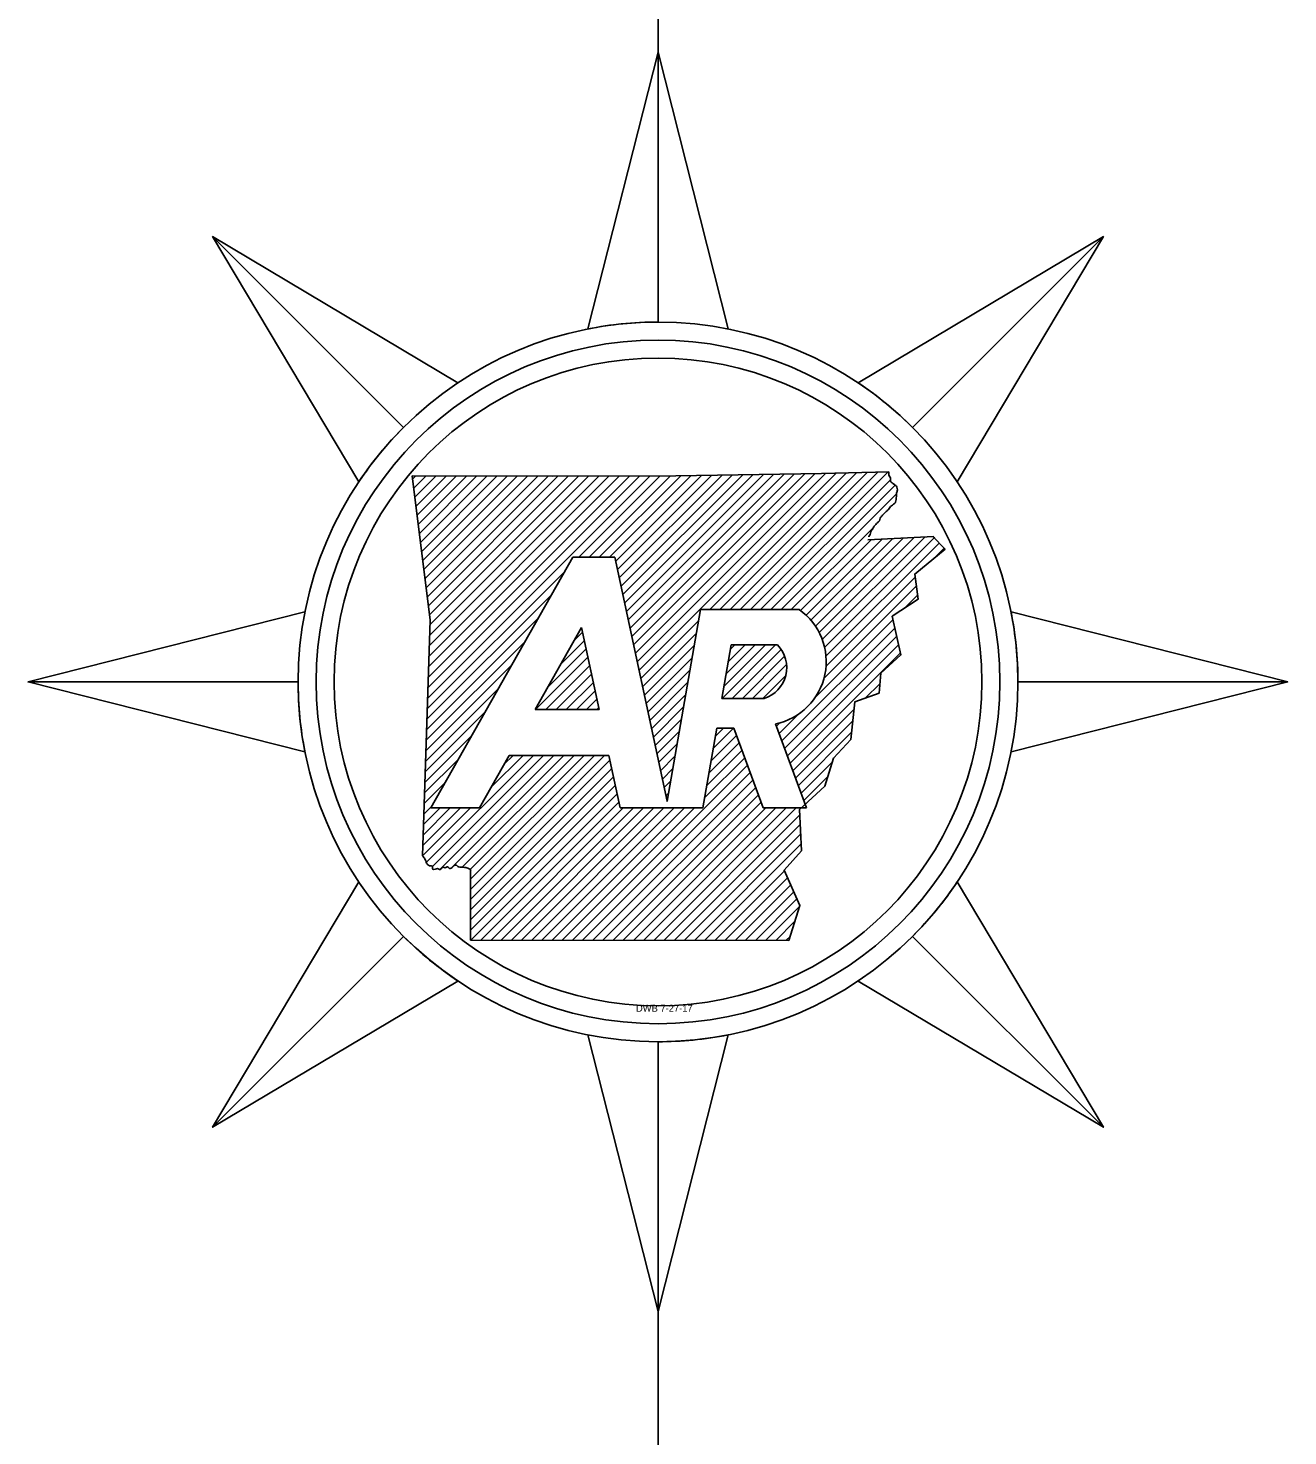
# Model space of a CAD drawing. Extents: x -4306 to 3843, y 131 to 8341.
# Drawn here: x 2356 to 2886, y 2831 to 3423 of the extents above; entities that cross this region are included whole.
import ezdxf

# ---------------------------------------------------------------- set-up
doc = ezdxf.new("R2010")
doc.units = 0
doc.layers.add('50', color=7, linetype='Continuous')

msp = doc.modelspace()

# ---------------------------------------------------------------- linework, layer by layer
at = {"layer": '50'}
for p, q in [((2621.3, 3912.98), (2621.3, 3315.55)), ((2621.3, 3412.53), (2591.83, 3296.13)), ((2621.3, 3299.03), (2621.3, 3412.53)), ((2434.03, 3334.96), (2514.29, 3254.71)), ((2514.29, 3254.71), (2434.03, 3334.96)), ((2434.03, 3334.96), (2495.5, 3231.82)), ((2808.56, 3334.96), (2705.42, 3273.49)), ((2728.3, 3254.71), (2808.56, 3334.96)), ((2728.3, 3254.71), (2808.56, 3334.96)), ((2518.14, 3232.99), (2519.48, 3234.33)), ((2518.62, 3229.19), (2523.76, 3234.32)), ((2519.09, 3225.38), (2528.03, 3234.32)), ((2519.57, 3221.57), (2532.31, 3234.32)), ((2520.04, 3217.77), (2536.59, 3234.32)), ((2520.52, 3213.96), (2540.87, 3234.31)), ((2520.99, 3210.15), (2545.15, 3234.31)), ((2521.46, 3206.35), (2549.42, 3234.31)), ((2521.94, 3202.54), (2553.7, 3234.3)), ((2522.41, 3198.74), (2557.98, 3234.3)), ((2522.89, 3194.93), (2562.26, 3234.3)), ((2523.36, 3191.12), (2566.53, 3234.3)), ((2523.83, 3187.32), (2570.81, 3234.29)), ((2524.31, 3183.51), (2575.09, 3234.29)), ((2524.45, 3140.85), (2617.98, 3234.38)), ((2524.6, 3145.28), (2613.69, 3234.37)), ((2524.74, 3149.71), (2609.4, 3234.36)), ((2524.78, 3179.7), (2579.37, 3234.3)), ((2524.89, 3154.13), (2605.11, 3234.35)), ((2525.04, 3158.56), (2600.82, 3234.34)), ((2525.18, 3162.99), (2596.53, 3234.33)), ((2525.26, 3175.9), (2583.66, 3234.3)), ((2525.33, 3167.41), (2592.24, 3234.32)), ((2525.48, 3171.84), (2587.95, 3234.31)), ((2588.01, 3200.13), (2622.27, 3234.39)), ((2592.29, 3200.13), (2626.56, 3234.4)), ((2596.57, 3200.13), (2630.87, 3234.43)), ((2600.85, 3200.13), (2635.22, 3234.5)), ((2603.52, 3198.52), (2639.57, 3234.57)), ((2604.27, 3194.99), (2643.92, 3234.63)), ((2605.03, 3191.47), (2648.26, 3234.7)), ((2605.78, 3187.94), (2652.61, 3234.77)), ((2606.54, 3184.42), (2656.96, 3234.84)), ((2607.29, 3180.89), (2661.31, 3234.9)), ((2608.05, 3177.36), (2665.65, 3234.97)), ((2608.8, 3173.84), (2670, 3235.04)), ((2609.56, 3170.31), (2674.35, 3235.11)), ((2610.31, 3166.79), (2678.7, 3235.17)), ((2611.06, 3163.26), (2683.05, 3235.24)), ((2611.82, 3159.74), (2687.39, 3235.31)), ((2612.57, 3156.21), (2691.75, 3235.39)), ((2613.33, 3152.68), (2696.14, 3235.49)), ((2643.06, 3178.14), (2700.52, 3235.59)), ((2647.34, 3178.14), (2704.9, 3235.7)), ((2651.62, 3178.14), (2709.28, 3235.8)), ((2655.9, 3178.14), (2713.66, 3235.9)), ((2660.18, 3178.14), (2718.05, 3236)), ((2664.46, 3178.14), (2719, 3232.67)), ((2668.74, 3178.14), (2721.07, 3230.46)), ((2673.02, 3178.14), (2721.62, 3226.74)), ((2677.3, 3178.14), (2711.85, 3212.68)), ((2690.36, 3165.52), (2733.57, 3208.72)), ((2681.19, 3177.75), (2711.01, 3207.56)), ((2683.53, 3175.8), (2715.52, 3207.79)), ((2685.62, 3173.61), (2720.03, 3208.02)), ((2687.47, 3171.18), (2724.54, 3208.26)), ((2689.06, 3168.49), (2729.06, 3208.49)), ((2691.35, 3162.22), (2737.63, 3208.5)), ((2691.93, 3158.52), (2739.63, 3206.22)), ((2737.73, 3200.04), (2741.63, 3203.94)), ((2525.72, 3094.69), (2585.43, 3200.13)), ((2585.43, 3200.13), (2603.17, 3200.13)), ((2524.3, 3136.42), (2582.06, 3194.18)), ((2691.95, 3154.26), (2729.42, 3191.73)), ((2691.06, 3149.09), (2729.91, 3187.94)), ((2524.16, 3132), (2576.47, 3184.31)), ((2725.11, 3178.86), (2730.4, 3184.15)), ((2524.01, 3127.57), (2570.89, 3174.44)), ((2614.08, 3149.16), (2638.37, 3173.45)), ((2639.19, 3178.14), (2680.65, 3178.14)), ((2687.34, 3141.09), (2720.04, 3173.79)), ((2886.12, 3147.7), (2769.73, 3177.17)), ((2569.65, 3136.07), (2589.17, 3170.56)), ((2586.14, 3165.2), (2589.58, 3168.65)), ((2614.84, 3145.63), (2637.47, 3168.26)), ((2673.39, 3122.86), (2720.84, 3170.31)), ((2523.86, 3123.14), (2565.3, 3164.58)), ((2574.96, 3145.47), (2591.09, 3161.6)), ((2580.55, 3155.33), (2590.34, 3165.12)), ((2615.59, 3142.11), (2636.56, 3163.08)), ((2648.21, 3140.74), (2670.73, 3163.25)), ((2649.09, 3145.89), (2666.45, 3163.25)), ((2649.99, 3151.07), (2662.17, 3163.25)), ((2650.89, 3156.26), (2657.89, 3163.25)), ((2651.8, 3161.44), (2653.61, 3163.25)), ((2652.11, 3163.25), (2671.58, 3163.25)), ((2652.49, 3140.74), (2673.11, 3161.35)), ((2674.54, 3119.73), (2721.64, 3166.83)), ((2675.7, 3116.61), (2722.44, 3163.35)), ((2569.85, 3136.07), (2591.85, 3158.07)), ((2616.35, 3138.58), (2635.66, 3157.89)), ((2656.77, 3140.74), (2674.55, 3158.52)), ((2676.85, 3113.48), (2723.24, 3159.87)), ((2523.72, 3118.72), (2559.71, 3154.71)), ((2574.13, 3136.07), (2592.6, 3154.55)), ((2578.41, 3136.07), (2593.36, 3151.02)), ((2617.1, 3135.05), (2634.76, 3152.71)), ((2661.05, 3140.74), (2675.35, 3155.03)), ((2665.33, 3140.74), (2674.99, 3150.39)), ((2356.47, 3147.7), (2469.97, 3147.7)), ((2469.97, 3147.7), (2356.47, 3147.7)), ((2356.47, 3147.7), (2472.86, 3118.23)), ((2523.57, 3114.29), (2554.12, 3144.84)), ((2582.69, 3136.07), (2594.11, 3147.49)), ((2586.97, 3136.07), (2594.87, 3143.97)), ((2617.86, 3131.53), (2633.85, 3147.53)), ((2708.61, 3140.96), (2714.61, 3146.96)), ((2772.63, 3147.7), (2886.12, 3147.7)), ((2772.63, 3147.7), (2886.12, 3147.7)), ((2591.25, 3136.07), (2595.62, 3140.44)), ((2618.61, 3128), (2632.95, 3142.34)), ((2648.19, 3140.74), (2665.97, 3140.74)), ((2523.42, 3109.86), (2548.53, 3134.97)), ((2569.65, 3136.07), (2596.56, 3136.07)), ((2595.53, 3136.07), (2596.38, 3136.92)), ((2619.36, 3124.48), (2632.05, 3137.16)), ((2620.12, 3120.95), (2631.14, 3131.98)), ((2672.23, 3125.98), (2680.38, 3134.13)), ((2678.01, 3110.36), (2703.68, 3136.03)), ((2620.87, 3117.43), (2630.24, 3126.79)), ((2644.52, 3119.67), (2653.07, 3128.22)), ((2645.42, 3124.85), (2648.79, 3128.22)), ((2653.19, 3128.22), (2646.01, 3128.22)), ((2665.58, 3094.69), (2653.19, 3128.22)), ((2670.74, 3130.01), (2683.8, 3094.69)), ((2671.08, 3129.11), (2672.38, 3130.41)), ((2679.16, 3107.23), (2703.2, 3131.27)), ((2680.32, 3104.1), (2702.72, 3126.51)), ((2523.28, 3105.43), (2542.95, 3125.11)), ((2621.63, 3113.9), (2629.34, 3121.61)), ((2642.71, 3109.3), (2655.47, 3122.06)), ((2643.61, 3114.48), (2654.31, 3125.19)), ((2523.13, 3101.01), (2537.36, 3115.24)), ((2523.91, 3071.83), (2568.9, 3116.81)), ((2526.45, 3070.09), (2573.18, 3116.81)), ((2529.53, 3068.88), (2577.46, 3116.81)), ((2534.61, 3069.69), (2581.74, 3116.81)), ((2538.96, 3069.75), (2586.02, 3116.81)), ((2542.31, 3068.83), (2590.3, 3116.81)), ((2542.46, 3064.69), (2594.58, 3116.81)), ((2542.47, 3060.42), (2598.86, 3116.81)), ((2542.48, 3056.15), (2601.11, 3114.79)), ((2558.74, 3116.81), (2546.21, 3094.69)), ((2551.06, 3103.26), (2564.62, 3116.81)), ((2556.65, 3113.13), (2560.34, 3116.81)), ((2600.68, 3116.81), (2558.74, 3116.81)), ((2622.38, 3110.37), (2628.43, 3116.43)), ((2640.9, 3098.93), (2657.78, 3115.81)), ((2641.81, 3104.12), (2656.62, 3118.93)), ((2681.47, 3100.98), (2694.6, 3114.1)), ((2542.49, 3051.88), (2601.87, 3111.26)), ((2585.31, 3039.06), (2658.93, 3112.68)), ((2589.59, 3039.06), (2660.09, 3109.56)), ((2623.14, 3106.85), (2627.53, 3111.24)), ((2682.63, 3097.85), (2692.76, 3107.99)), ((2522.98, 3096.58), (2531.77, 3105.37)), ((2542.5, 3047.61), (2602.62, 3107.73)), ((2542.51, 3043.34), (2603.37, 3104.21)), ((2593.86, 3039.05), (2661.24, 3106.43)), ((2598.13, 3039.04), (2662.4, 3103.31)), ((2623.89, 3103.32), (2626.63, 3106.06)), ((2542.58, 3039.13), (2604.13, 3100.68)), ((2546.85, 3039.13), (2604.88, 3097.16)), ((2602.41, 3039.04), (2663.55, 3100.18)), ((2606.68, 3039.03), (2664.71, 3097.06)), ((2624.65, 3099.8), (2625.72, 3100.87)), ((2522.31, 3074.51), (2542.49, 3094.69)), ((2522.39, 3078.87), (2538.21, 3094.69)), ((2522.54, 3083.3), (2533.93, 3094.69)), ((2522.69, 3087.73), (2529.65, 3094.69)), ((2522.84, 3092.15), (2526.18, 3095.5)), ((2546.21, 3094.69), (2525.72, 3094.69)), ((2551.13, 3039.12), (2606.69, 3094.69)), ((2555.4, 3039.11), (2610.97, 3094.69)), ((2559.67, 3039.11), (2615.25, 3094.69)), ((2563.95, 3039.1), (2619.53, 3094.69)), ((2568.22, 3039.09), (2623.81, 3094.69)), ((2572.49, 3039.09), (2628.1, 3094.69)), ((2576.77, 3039.08), (2632.38, 3094.69)), ((2581.04, 3039.07), (2636.66, 3094.69)), ((2640.16, 3094.69), (2605.41, 3094.69)), ((2610.95, 3039.02), (2666.62, 3094.69)), ((2615.23, 3039.02), (2670.9, 3094.69)), ((2619.5, 3039.01), (2675.18, 3094.69)), ((2623.77, 3039), (2679.46, 3094.69)), ((2628.05, 3038.99), (2680.89, 3091.84)), ((2683.8, 3094.69), (2665.58, 3094.69)), ((2632.32, 3038.99), (2681.08, 3087.75)), ((2636.59, 3038.98), (2681.27, 3083.66)), ((2640.87, 3038.97), (2681.47, 3079.57)), ((2645.14, 3038.97), (2674.44, 3068.26)), ((2649.41, 3038.96), (2675.76, 3065.3)), ((2653.69, 3038.95), (2677.08, 3062.34)), ((2808.56, 2960.44), (2747.09, 3063.58)), ((2657.96, 3038.95), (2678.4, 3059.39)), ((2662.23, 3038.94), (2679.72, 3056.43)), ((2666.51, 3038.93), (2680.83, 3053.25)), ((2670.78, 3038.92), (2678.89, 3047.03)), ((2434.03, 2960.44), (2514.29, 3040.69)), ((2514.29, 3040.69), (2434.03, 2960.44)), ((2675.05, 3038.92), (2676.95, 3040.82)), ((2728.3, 3040.69), (2808.56, 2960.44)), ((2728.3, 3040.69), (2808.56, 2960.44)), ((2434.03, 2960.44), (2537.18, 3021.9)), ((2621.29, 2996.37), (2621.3, 2996.38)), ((2621.3, 2882.87), (2650.76, 2999.27)), ((2621.3, 2996.37), (2621.3, 2511.93)), ((2621.3, 2996.37), (2621.3, 2882.87))]:
    msp.add_line(p, q, dxfattribs=at)
for points in [[(2591.83, 3296.13), (2621.3, 3412.53), (2650.76, 3296.13)], [(2495.5, 3231.82), (2434.03, 3334.96), (2537.18, 3273.49)], [(2705.42, 3273.49), (2808.56, 3334.96), (2747.09, 3231.82)], [(2517.98, 3234.33), (2577.03, 3234.29), (2628.85, 3234.4), (2689.98, 3235.35), (2718.32, 3236.01)], [(2522.25, 3074.56), (2525.54, 3173.63), (2517.98, 3234.33)], [(2736.87, 3208.87), (2741.98, 3203.54), (2729.24, 3193.07), (2730.62, 3182.49), (2719.69, 3175.29), (2723.43, 3159.03), (2715.01, 3151.35), (2714.26, 3142.99), (2704.01, 3139.31), (2702.42, 3123.55), (2695.06, 3115.67), (2691.51, 3103.8), (2680.79, 3093.99), (2681.6, 3076.68), (2674.32, 3068.52), (2680.96, 3053.67), (2676.36, 3038.92)], [(2709.56, 3207.49), (2737.27, 3208.91)], [(2603.17, 3200.13), (2625.14, 3097.51), (2639.19, 3178.14)], [(2472.86, 3118.23), (2356.47, 3147.7), (2472.86, 3177.17)], [(2769.73, 3177.17), (2886.12, 3147.7), (2769.73, 3118.23)], [(2589.17, 3170.56), (2596.56, 3136.07)], [(2648.19, 3140.74), (2652.11, 3163.25)], [(2646.01, 3128.22), (2640.16, 3094.69)], [(2605.41, 3094.69), (2600.68, 3116.81)], [(2676.36, 3038.92), (2542.52, 3039.13), (2542.45, 3068.68)], [(2537.18, 3021.9), (2434.03, 2960.44), (2495.5, 3063.58)], [(2747.09, 3063.58), (2808.56, 2960.44), (2705.42, 3021.9)], [(2650.76, 2999.27), (2621.3, 2882.87), (2591.83, 2999.27)]]:
    msp.add_lwpolyline(points, dxfattribs=at)
for radius in [151.33, 143.76, 136.2]:
    msp.add_circle((2621.3, 3147.7), radius, dxfattribs=at)
for centre, radius, start, end in [((2621.3, 3147.7), 151.33, 90, 101.22909), ((2621.3, 3147.7), 151.33, 45, 56.22909), ((2621.3, 3147.7), 151.33, 135, 146.22909), ((2665.24, 3156.23), 26.79, 281.86262, 54.87052), ((2621.3, 3147.7), 151.33, 0, 11.22909), ((2661.71, 3153.76), 13.7, 288.12683, 43.89016), ((2621.3, 3147.7), 151.33, 180, 191.22909), ((2621.3, 3147.7), 151.33, 315, 326.22909), ((2621.3, 3147.7), 151.33, 225, 236.22909), ((2621.3, 3147.7), 151.33, 270, 281.22909)]:
    msp.add_arc(centre, radius, start, end, dxfattribs=at)
for points in [[(2718.32, 3236.01), (2718.5, 3234.4), (2719.01, 3233.56), (2719.09, 3232.03), (2719.71, 3231.37), (2720.77, 3230.71), (2721.72, 3229.65), (2721.94, 3228.41), (2721.64, 3227.13), (2721.57, 3225.71), (2721.42, 3224.47), (2721.21, 3223.33), (2720.33, 3222.42), (2719.49, 3221.76), (2718.72, 3221), (2718.17, 3220.19), (2717.22, 3219.32), (2716.28, 3218.4), (2715.51, 3217.6), (2714.74, 3216.58), (2714.38, 3215.45), (2713.54, 3214.64), (2712.88, 3213.91), (2712, 3212.93), (2711.56, 3211.94), (2710.72, 3210.81), (2710.54, 3209.71), (2709.99, 3208.84), (2709.96, 3208.69)], [(2542.45, 3068.68), (2542.59, 3068.6), (2541.9, 3069.08), (2540.95, 3069.55), (2539.89, 3069.63), (2538.54, 3069.81), (2537.41, 3069.92), (2536.24, 3070.69), (2535, 3069.88), (2533.61, 3069.3), (2532.81, 3069.96), (2531.75, 3069.52), (2531.02, 3069.74), (2529.74, 3068.86), (2528.53, 3069.19), (2527.66, 3068.93), (2526.56, 3068.97), (2526.34, 3070.21), (2525.28, 3070.39), (2524.37, 3070.91), (2523.75, 3072.18), (2523.31, 3073.17), (2522.25, 3074.56)]]:
    msp.add_spline(points, degree=3, dxfattribs=at)

# ---------------------------------------------------------------- texts
msp.add_text('DWB 7-27-17', height=2.9425, dxfattribs=at).set_placement((2612.03, 3008.98))

doc.saveas('drawing.dxf')
